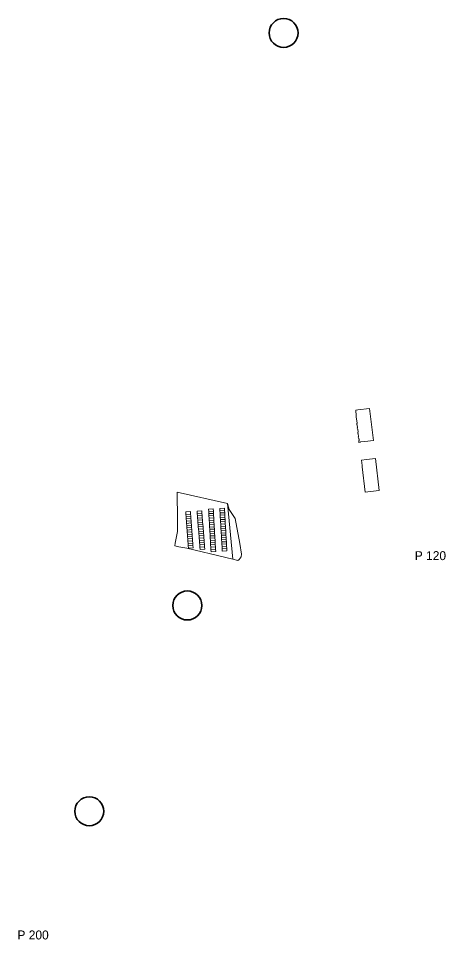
# Model space of a CAD drawing. Extents: x -648438 to -645379, y -1072966 to -1066997.
# Drawn here: x -645951 to -645379, y -1071281 to -1070047 of the extents above; entities that cross this region are included whole.
import ezdxf

# ---------------------------------------------------------------- set-up
doc = ezdxf.new("R2010")
doc.units = 0
doc.header["$LTSCALE"] = 4
doc.layers.add('40', color=7, linetype='Continuous', lineweight=13)
doc.layers.add('56', color=7, linetype='Continuous')

msp = doc.modelspace()

# ---------------------------------------------------------------- linework, layer by layer
at = {"layer": '40'}
for p, q in [((-645690.19, -1070703.82), (-645696.38, -1070704.17)), ((-645675.17, -1070702.92), (-645681.4, -1070703.28))]:
    msp.add_line(p, q, dxfattribs=at)
for points in [[(-645499.25, -1070571.93), (-645496.52, -1070571.56), (-645480.56, -1070569.79), (-645475.56, -1070612.43), (-645487.19, -1070613.79), (-645492.84, -1070614.42), (-645492.81, -1070614.88), (-645494.88, -1070615.07), (-645495.08, -1070613.33), (-645494.56, -1070613.26), (-645494.7, -1070612.17), (-645495.08, -1070612.22), (-645495.15, -1070611.38), (-645494.78, -1070611.36), (-645495.06, -1070609.1), (-645495.56, -1070609.16), (-645495.76, -1070607.36), (-645495.26, -1070607.33), (-645495.72, -1070603.18), (-645496.25, -1070603.23), (-645496.47, -1070601.42), (-645495.92, -1070601.39), (-645496.42, -1070597.2), (-645496.94, -1070597.25), (-645497.12, -1070595.47), (-645496.64, -1070595.38), (-645497.09, -1070591.24), (-645497.6, -1070591.26), (-645497.88, -1070589.46), (-645497.3, -1070589.44), (-645498.42, -1070580.7), (-645498.6, -1070579.19)], [(-645491.49, -1070638.79), (-645484.53, -1070637.98), (-645472.8, -1070636.65), (-645467.82, -1070679.26), (-645479.54, -1070680.67), (-645486.67, -1070681.54), (-645490.59, -1070647.61), (-645490.75, -1070646.01)], [(-645741.73, -1070753.43), (-645741.06, -1070749.97), (-645737.99, -1070734.24), (-645737.9, -1070733.79), (-645738.04, -1070706.52), (-645738.27, -1070693.6), (-645738.54, -1070681.67), (-645670.99, -1070696.59), (-645663.85, -1070771.25), (-645673.13, -1070768.85), (-645725.53, -1070756.73), (-645736.14, -1070754.57)], [(-645670.99, -1070696.59), (-645668.66, -1070704.8), (-645660.67, -1070716.93), (-645654.45, -1070750.47), (-645652.23, -1070764.39), (-645652.92, -1070768.33), (-645655.3, -1070771.84), (-645656.99, -1070773.02), (-645663.85, -1070771.25)], [(-645727.04, -1070708.12), (-645720.71, -1070707.65), (-645720.47, -1070710.84), (-645726.8, -1070711.36)], [(-645727.04, -1070708.12), (-645726.8, -1070711.36), (-645726.58, -1070714.35), (-645726.36, -1070717.35), (-645726.14, -1070720.34), (-645725.91, -1070723.33), (-645725.69, -1070726.32), (-645725.47, -1070729.31), (-645725.25, -1070732.31), (-645725.03, -1070735.3), (-645724.81, -1070738.29), (-645724.58, -1070741.28), (-645724.36, -1070744.27), (-645724.14, -1070747.26), (-645723.92, -1070750.26), (-645723.7, -1070753.25), (-645723.46, -1070756.44), (-645717.13, -1070755.97), (-645717.37, -1070752.73), (-645717.59, -1070749.74), (-645717.81, -1070746.74), (-645718.03, -1070743.75), (-645718.26, -1070740.76), (-645718.48, -1070737.77), (-645718.7, -1070734.78), (-645718.92, -1070731.78), (-645719.14, -1070728.79), (-645719.36, -1070725.8), (-645719.59, -1070722.81), (-645719.81, -1070719.82), (-645720.03, -1070716.83), (-645720.25, -1070713.83), (-645720.47, -1070710.84), (-645720.71, -1070707.65)], [(-645726.8, -1070711.36), (-645720.47, -1070710.84), (-645720.25, -1070713.83), (-645726.58, -1070714.35)], [(-645711.81, -1070707.07), (-645705.53, -1070706.57), (-645705.28, -1070709.76), (-645711.56, -1070710.26)], [(-645711.81, -1070707.07), (-645711.56, -1070710.26), (-645711.32, -1070713.25), (-645711.08, -1070716.24), (-645710.85, -1070719.23), (-645710.61, -1070722.22), (-645710.37, -1070725.21), (-645710.14, -1070728.2), (-645709.9, -1070731.19), (-645709.66, -1070734.19), (-645709.43, -1070737.18), (-645709.19, -1070740.17), (-645708.95, -1070743.16), (-645708.71, -1070746.15), (-645708.48, -1070749.14), (-645708.24, -1070752.13), (-645708, -1070755.12), (-645707.75, -1070758.31), (-645701.47, -1070757.81), (-645701.72, -1070754.62), (-645701.96, -1070751.63), (-645702.2, -1070748.64), (-645702.43, -1070745.65), (-645702.67, -1070742.66), (-645702.91, -1070739.67), (-645703.15, -1070736.68), (-645703.38, -1070733.68), (-645703.62, -1070730.69), (-645703.85, -1070727.7), (-645704.09, -1070724.71), (-645704.33, -1070721.72), (-645704.57, -1070718.73), (-645704.8, -1070715.74), (-645705.04, -1070712.75), (-645705.28, -1070709.76), (-645705.53, -1070706.57)], [(-645711.56, -1070710.26), (-645705.28, -1070709.76), (-645705.04, -1070712.75), (-645711.32, -1070713.25)], [(-645711.32, -1070713.25), (-645705.04, -1070712.75), (-645704.8, -1070715.74), (-645711.08, -1070716.24)], [(-645696.38, -1070704.17), (-645690.19, -1070703.82), (-645690, -1070706.99), (-645696.2, -1070707.34)], [(-645696.2, -1070707.34), (-645690, -1070706.99), (-645689.83, -1070709.98), (-645696.02, -1070710.33)], [(-645696.02, -1070710.33), (-645689.83, -1070709.98), (-645689.65, -1070712.98), (-645695.85, -1070713.33)], [(-645695.85, -1070713.33), (-645689.65, -1070712.98), (-645689.47, -1070715.97), (-645695.67, -1070716.32)], [(-645681.4, -1070703.28), (-645675.17, -1070702.92), (-645674.98, -1070706.06), (-645681.21, -1070706.42)], [(-645681.21, -1070706.42), (-645674.98, -1070706.06), (-645674.81, -1070709.05), (-645681.04, -1070709.41)], [(-645681.04, -1070709.41), (-645674.81, -1070709.05), (-645674.63, -1070712.04), (-645680.86, -1070712.4)], [(-645680.86, -1070712.4), (-645674.63, -1070712.04), (-645674.46, -1070715.03), (-645680.69, -1070715.39)], [(-645726.58, -1070714.35), (-645720.25, -1070713.83), (-645720.03, -1070716.83), (-645726.36, -1070717.35)], [(-645726.36, -1070717.35), (-645720.03, -1070716.83), (-645719.81, -1070719.82), (-645726.14, -1070720.34)], [(-645726.14, -1070720.34), (-645719.81, -1070719.82), (-645719.59, -1070722.81), (-645725.91, -1070723.33)], [(-645725.91, -1070723.33), (-645719.59, -1070722.81), (-645719.36, -1070725.8), (-645725.69, -1070726.32)], [(-645711.08, -1070716.24), (-645704.8, -1070715.74), (-645704.57, -1070718.73), (-645710.85, -1070719.23)], [(-645710.85, -1070719.23), (-645704.57, -1070718.73), (-645704.33, -1070721.72), (-645710.61, -1070722.22)], [(-645710.61, -1070722.22), (-645704.33, -1070721.72), (-645704.09, -1070724.71), (-645710.37, -1070725.21)], [(-645710.37, -1070725.21), (-645704.09, -1070724.71), (-645703.85, -1070727.7), (-645710.14, -1070728.2)], [(-645689.3, -1070718.96), (-645689.47, -1070715.97), (-645695.67, -1070716.32), (-645695.5, -1070719.31)], [(-645695.5, -1070719.31), (-645689.3, -1070718.96), (-645689.12, -1070721.95), (-645695.32, -1070722.31)], [(-645695.32, -1070722.31), (-645689.12, -1070721.95), (-645688.94, -1070724.94), (-645695.15, -1070725.3)], [(-645695.15, -1070725.3), (-645688.94, -1070724.94), (-645688.77, -1070727.94), (-645694.98, -1070728.29)], [(-645680.69, -1070715.39), (-645674.46, -1070715.03), (-645674.28, -1070718.02), (-645680.51, -1070718.39)], [(-645680.51, -1070718.39), (-645674.28, -1070718.02), (-645674.1, -1070721.01), (-645680.33, -1070721.38)], [(-645680.33, -1070721.38), (-645674.1, -1070721.01), (-645673.93, -1070724), (-645680.16, -1070724.37)], [(-645680.16, -1070724.37), (-645673.93, -1070724), (-645673.75, -1070726.99), (-645679.98, -1070727.36)], [(-645725.69, -1070726.32), (-645719.36, -1070725.8), (-645719.14, -1070728.79), (-645725.47, -1070729.31)], [(-645725.47, -1070729.31), (-645719.14, -1070728.79), (-645718.92, -1070731.78), (-645725.25, -1070732.31)], [(-645725.25, -1070732.31), (-645718.92, -1070731.78), (-645718.7, -1070734.78), (-645725.03, -1070735.3)], [(-645725.03, -1070735.3), (-645718.7, -1070734.78), (-645718.48, -1070737.77), (-645724.81, -1070738.29)], [(-645710.14, -1070728.2), (-645703.85, -1070727.7), (-645703.62, -1070730.69), (-645709.9, -1070731.19)], [(-645709.9, -1070731.19), (-645703.62, -1070730.69), (-645703.38, -1070733.68), (-645709.66, -1070734.19)], [(-645709.66, -1070734.19), (-645703.38, -1070733.68), (-645703.15, -1070736.68), (-645709.43, -1070737.18)], [(-645709.43, -1070737.18), (-645703.15, -1070736.68), (-645702.91, -1070739.67), (-645709.19, -1070740.17)], [(-645694.98, -1070728.29), (-645688.77, -1070727.94), (-645688.59, -1070730.93), (-645694.8, -1070731.28)], [(-645694.8, -1070731.28), (-645688.59, -1070730.93), (-645688.42, -1070733.92), (-645694.63, -1070734.28)], [(-645694.63, -1070734.28), (-645688.42, -1070733.92), (-645688.24, -1070736.91), (-645694.45, -1070737.27)], [(-645694.45, -1070737.27), (-645688.24, -1070736.91), (-645688.06, -1070739.91), (-645694.28, -1070740.26)], [(-645679.98, -1070727.36), (-645673.75, -1070726.99), (-645673.57, -1070729.98), (-645679.8, -1070730.35)], [(-645679.8, -1070730.35), (-645673.57, -1070729.98), (-645673.4, -1070732.98), (-645679.63, -1070733.34)], [(-645679.63, -1070733.34), (-645673.4, -1070732.98), (-645673.22, -1070735.97), (-645679.45, -1070736.33)], [(-645679.45, -1070736.33), (-645673.22, -1070735.97), (-645673.05, -1070738.96), (-645679.28, -1070739.32)], [(-645724.81, -1070738.29), (-645718.48, -1070737.77), (-645718.26, -1070740.76), (-645724.58, -1070741.28)], [(-645724.58, -1070741.28), (-645718.26, -1070740.76), (-645718.03, -1070743.75), (-645724.36, -1070744.27)], [(-645724.36, -1070744.27), (-645718.03, -1070743.75), (-645717.81, -1070746.74), (-645724.14, -1070747.26)], [(-645724.14, -1070747.26), (-645717.81, -1070746.74), (-645717.59, -1070749.74), (-645723.92, -1070750.26)], [(-645723.92, -1070750.26), (-645717.59, -1070749.74), (-645717.37, -1070752.73), (-645723.7, -1070753.25)], [(-645709.19, -1070740.17), (-645702.91, -1070739.67), (-645702.67, -1070742.66), (-645708.95, -1070743.16)], [(-645708.95, -1070743.16), (-645702.67, -1070742.66), (-645702.43, -1070745.65), (-645708.71, -1070746.15)], [(-645708.71, -1070746.15), (-645702.43, -1070745.65), (-645702.2, -1070748.64), (-645708.48, -1070749.14)], [(-645708.48, -1070749.14), (-645702.2, -1070748.64), (-645701.96, -1070751.63), (-645708.24, -1070752.13)], [(-645694.28, -1070740.26), (-645688.06, -1070739.91), (-645687.89, -1070742.9), (-645694.1, -1070743.25)], [(-645694.1, -1070743.25), (-645687.89, -1070742.9), (-645687.71, -1070745.89), (-645693.93, -1070746.25)], [(-645693.93, -1070746.25), (-645687.71, -1070745.89), (-645687.53, -1070748.88), (-645693.76, -1070749.24)], [(-645693.76, -1070749.24), (-645687.53, -1070748.88), (-645687.36, -1070751.87), (-645693.58, -1070752.23)], [(-645679.28, -1070739.32), (-645673.05, -1070738.96), (-645672.87, -1070741.95), (-645679.1, -1070742.31)], [(-645679.1, -1070742.31), (-645672.87, -1070741.95), (-645672.69, -1070744.94), (-645678.92, -1070745.31)], [(-645678.92, -1070745.31), (-645672.69, -1070744.94), (-645672.52, -1070747.93), (-645678.75, -1070748.3)], [(-645678.75, -1070748.3), (-645672.52, -1070747.93), (-645672.34, -1070750.92), (-645678.57, -1070751.29)], [(-645723.7, -1070753.25), (-645717.37, -1070752.73), (-645717.13, -1070755.97), (-645723.46, -1070756.44)], [(-645708.24, -1070752.13), (-645701.96, -1070751.63), (-645701.72, -1070754.62), (-645708, -1070755.12)], [(-645708, -1070755.12), (-645701.72, -1070754.62), (-645701.47, -1070757.81), (-645707.75, -1070758.31)], [(-645693.58, -1070752.23), (-645687.36, -1070751.87), (-645687.18, -1070754.87), (-645693.41, -1070755.23)], [(-645693.41, -1070755.23), (-645687.18, -1070754.87), (-645687.01, -1070757.86), (-645693.23, -1070758.21)], [(-645693.23, -1070758.21), (-645687.01, -1070757.86), (-645686.82, -1070761), (-645693.05, -1070761.36)], [(-645678.57, -1070751.29), (-645672.34, -1070750.92), (-645672.16, -1070753.91), (-645678.39, -1070754.28)], [(-645678.39, -1070754.28), (-645672.16, -1070753.91), (-645671.99, -1070756.9), (-645678.22, -1070757.27)], [(-645678.22, -1070757.27), (-645671.99, -1070756.9), (-645671.71, -1070760.2), (-645678.03, -1070760.46)]]:
    msp.add_lwpolyline(points, close=True, dxfattribs=at)
for points in [[(-645696.38, -1070704.17), (-645696.2, -1070707.34), (-645696.02, -1070710.33), (-645695.85, -1070713.33), (-645695.67, -1070716.32), (-645695.5, -1070719.31), (-645695.32, -1070722.31), (-645695.15, -1070725.3), (-645694.98, -1070728.29), (-645694.8, -1070731.28), (-645694.63, -1070734.28), (-645694.45, -1070737.27), (-645694.28, -1070740.26), (-645694.1, -1070743.25), (-645693.93, -1070746.25), (-645693.76, -1070749.24), (-645693.58, -1070752.23), (-645693.41, -1070755.23), (-645693.23, -1070758.21), (-645693.05, -1070761.36), (-645686.82, -1070761), (-645687.01, -1070757.86), (-645687.18, -1070754.87), (-645687.36, -1070751.87), (-645687.53, -1070748.88), (-645687.71, -1070745.89), (-645687.89, -1070742.9), (-645688.06, -1070739.91), (-645688.24, -1070736.91), (-645688.42, -1070733.92), (-645688.59, -1070730.93), (-645688.77, -1070727.94), (-645688.94, -1070724.94), (-645689.12, -1070721.95), (-645689.3, -1070718.96), (-645689.47, -1070715.97), (-645689.65, -1070712.98), (-645689.83, -1070709.98), (-645690, -1070706.99), (-645690.19, -1070703.82)], [(-645681.4, -1070703.28), (-645681.21, -1070706.42), (-645681.04, -1070709.41), (-645680.86, -1070712.4), (-645680.69, -1070715.39), (-645680.51, -1070718.39), (-645680.33, -1070721.38), (-645680.16, -1070724.37), (-645679.98, -1070727.36), (-645679.8, -1070730.35), (-645679.63, -1070733.34), (-645679.45, -1070736.33), (-645679.28, -1070739.32), (-645679.1, -1070742.31), (-645678.92, -1070745.31), (-645678.75, -1070748.3), (-645678.57, -1070751.29), (-645678.39, -1070754.28), (-645678.22, -1070757.27), (-645678.03, -1070760.46), (-645671.71, -1070760.2), (-645671.99, -1070756.9), (-645672.16, -1070753.91), (-645672.34, -1070750.92), (-645672.52, -1070747.93), (-645672.69, -1070744.94), (-645672.87, -1070741.95), (-645673.05, -1070738.96), (-645673.22, -1070735.97), (-645673.4, -1070732.98), (-645673.57, -1070729.98), (-645673.75, -1070726.99), (-645673.93, -1070724), (-645674.1, -1070721.01), (-645674.28, -1070718.02), (-645674.46, -1070715.03), (-645674.63, -1070712.04), (-645674.81, -1070709.05), (-645674.98, -1070706.06), (-645675.17, -1070702.92)]]:
    msp.add_lwpolyline(points, dxfattribs=at)
at = {"layer": '40', "lineweight": 35}
for centre in [(-645595.813, -1070066.769), (-645724.847, -1070833.283), (-645856.201, -1071108.851)]:
    msp.add_circle(centre, 19.412, dxfattribs=at)

# ---------------------------------------------------------------- texts
at = {"layer": '56'}
for s, p in [('P 120', (-645420.051, -1070772.597)), ('P 200', (-645952.553, -1071280.415))]:
    msp.add_text(s, height=12, dxfattribs=at).set_placement(p)

doc.saveas('drawing.dxf')
